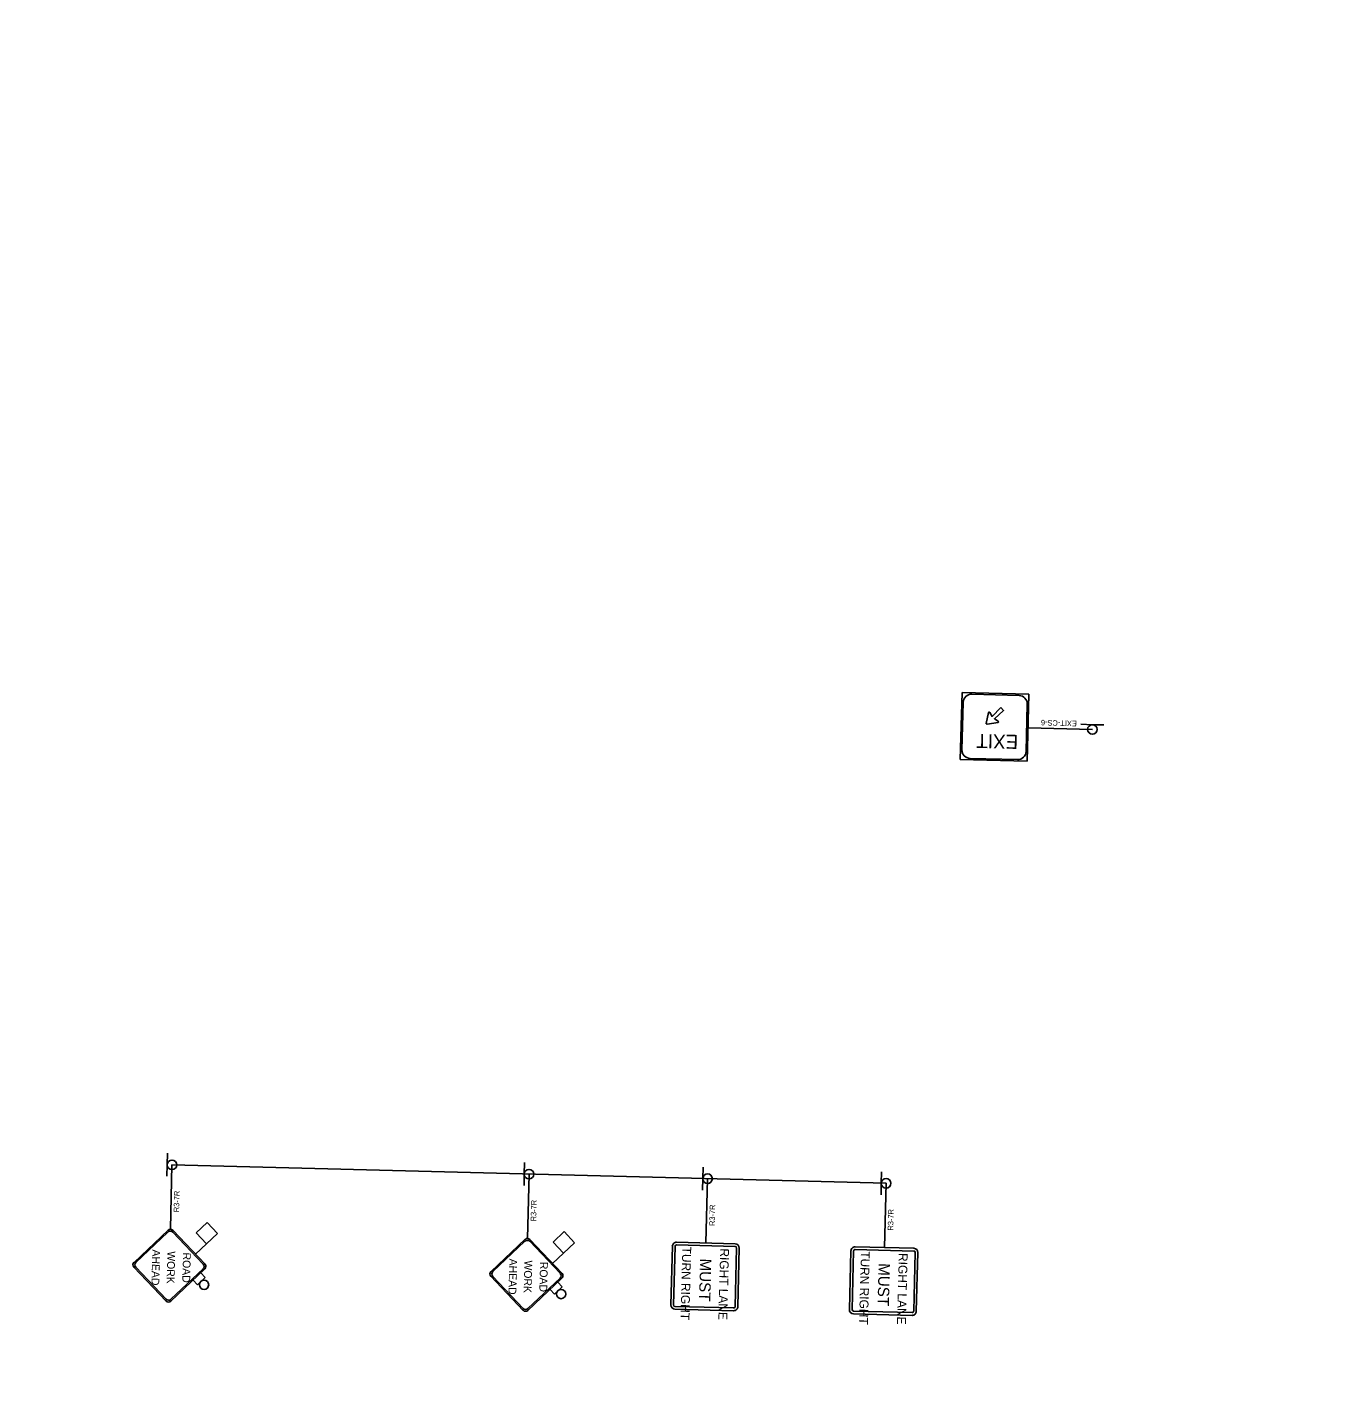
# Model space of a CAD drawing. Extents: x 2135767 to 2151731, y 141839 to 175894.
# Drawn here: x 2139087 to 2140193, y 169570 to 170711 of the extents above; entities that cross this region are included whole.
import ezdxf

# ---------------------------------------------------------------- set-up
doc = ezdxf.new("R2010")
doc.units = 0
for name, color, linetype in [('Default', 7, 'Continuous'), ('PR_Phasing_Detour_1', 7, 'Continuous'), ('PR_Traffic_Sign_Temp', 7, 'Continuous'), ('PR_Txt', 7, 'Continuous')]:
    doc.layers.add(name, color=color, linetype=linetype)

# ---------------------------------------------------------------- blocks, each defined once
blk = doc.blocks.new('FLSHFLAG')
at = {"layer": 'PR_Txt'}
for p, q in [((-1.2, 14.13), (0.84, 16.15)), ((0.84, 16.15), (4.9, 12.08)), ((0.82, 12.08), (-1.2, 14.13)), ((0.82, 12.08), (2.86, 14.11)), ((9.26, 14), (8.4, 13.15)), ((9.26, 14), (10.68, 12.58)), ((10.68, 12.58), (9.83, 11.72))]:
    blk.add_line(p, q, dxfattribs=at)
blk.add_circle((10.65, 13.84), 0.873, dxfattribs=at)

msp = doc.modelspace()

# ---------------------------------------------------------------- linework, layer by layer
at = {"layer": 'Default'}
for p, q in [((2139871.8, 170151.9), (2139870.3, 170095.6)), ((2139928, 170150.4), (2139871.8, 170151.9)), ((2139926.6, 170094.2), (2139928, 170150.4)), ((2139904.5, 170139.3), (2139897, 170131.9)), ((2139906.7, 170136.8), (2139904.5, 170139.3)), ((2139894, 170135.2), (2139892.1, 170126)), ((2139892.8, 170125.4), (2139902.1, 170126.8)), ((2139897, 170131.9), (2139895.2, 170135.1)), ((2139899, 170129.9), (2139906.7, 170136.8)), ((2139902.3, 170127.8), (2139899, 170129.9)), ((2139870.3, 170095.6), (2139926.6, 170094.2)), ((2139204.9, 169700.3), (2139176.3, 169673.2)), ((2139204.8, 169698.7), (2139177.9, 169673.2)), ((2139236, 169671.7), (2139208.8, 169700.2)), ((2139234.4, 169671.7), (2139208.8, 169698.6)), ((2139504.8, 169692.6), (2139476.2, 169665.5)), ((2139504.7, 169691), (2139477.8, 169665.4)), ((2139535.9, 169663.9), (2139508.7, 169692.5)), ((2139534.3, 169664), (2139508.7, 169690.9)), ((2139628.5, 169686.7), (2139627.2, 169637.5)), ((2139630.8, 169686.6), (2139629.5, 169637.4)), ((2139681.3, 169688.8), (2139632.1, 169690.1)), ((2139681.3, 169686.6), (2139632.1, 169687.9)), ((2139681.2, 169636.1), (2139682.5, 169685.3)), ((2139683.5, 169636), (2139684.7, 169685.2)), ((2139778.5, 169682.8), (2139777.2, 169633.6)), ((2139780.7, 169682.8), (2139779.4, 169633.6)), ((2139831.2, 169682.7), (2139782, 169684)), ((2139831.3, 169685), (2139782.1, 169686.2)), ((2139831.2, 169632.2), (2139832.4, 169681.4)), ((2139833.4, 169632.2), (2139834.7, 169681.4)), ((2139176.2, 169669.2), (2139203.3, 169640.7)), ((2139177.8, 169669.2), (2139203.4, 169642.3)), ((2139207.3, 169642.2), (2139234.3, 169667.7)), ((2139207.3, 169640.6), (2139235.8, 169667.7)), ((2139476.1, 169661.5), (2139503.2, 169632.9)), ((2139477.7, 169661.4), (2139503.3, 169634.5)), ((2139507.2, 169634.4), (2139534.2, 169660)), ((2139507.2, 169632.8), (2139535.7, 169659.9)), ((2139630.7, 169636.1), (2139679.9, 169634.9)), ((2139630.7, 169633.9), (2139679.9, 169632.6)), ((2139780.6, 169630), (2139829.8, 169628.7)), ((2139780.7, 169632.3), (2139829.9, 169631))]:
    msp.add_line(p, q, dxfattribs=at)
for points in [[(2139919.8, 170149.5), (2139880, 170150.5)], [(2139872.8, 170143.6), (2139871.7, 170103.8)], [(2139904.5, 170139.3), (2139897, 170131.9), (2139895.2, 170135.1)], [(2139902.3, 170127.8), (2139899, 170129.9), (2139906.7, 170136.8), (2139904.5, 170139.3)], [(2139925.6, 170102.4), (2139926.6, 170142.2)], [(2139894, 170135.2), (2139892.1, 170126)], [(2139892.8, 170125.4), (2139902.1, 170126.8)], [(2139878.6, 170096.6), (2139918.4, 170095.6)]]:
    msp.add_lwpolyline(points, dxfattribs=at)
for centre, radius, start, end in [((2139879.8, 170143.5), 7.03, 88.5212, 178.5212), ((2139919.6, 170142.4), 7.03, 358.5212, 88.5212), ((2139894.6, 170134.8), 0.699, 29.5789, 144.6011), ((2139894.6, 170134.8), 0.699, 29.5789, 144.6011), ((2139902.1, 170127.3), 0.507, 278.9476, 67.6995), ((2139902.1, 170127.3), 0.507, 278.9476, 67.6995), ((2139892.6, 170125.9), 0.543, 168.0494, 293.8906), ((2139892.6, 170125.9), 0.543, 168.0494, 293.8906), ((2139878.8, 170103.6), 7.03, 178.5212, 268.5212), ((2139918.6, 170102.6), 7.03, 268.5212, 358.5212), ((2139206.8, 169696.7), 2.81, 43.5212, 133.5212), ((2139206.8, 169698.3), 2.81, 43.5212, 133.5212), ((2139506.7, 169690.5), 2.81, 43.5212, 133.5212), ((2139506.7, 169688.9), 2.81, 43.5212, 133.5212), ((2139632, 169686.6), 3.52, 88.5212, 178.5212), ((2139632, 169686.6), 1.27, 88.5212, 178.5212), ((2139681.2, 169685.3), 3.52, 358.5212, 88.5212), ((2139681.2, 169685.3), 1.27, 358.5212, 88.5212), ((2139782, 169682.7), 3.52, 88.5212, 178.5212), ((2139782, 169682.7), 1.27, 88.5212, 178.5212), ((2139831.2, 169681.5), 1.27, 358.5212, 88.5212), ((2139831.2, 169681.5), 3.52, 358.5212, 88.5212), ((2139178.2, 169671.2), 2.81, 133.5212, 223.5212), ((2139179.8, 169671.1), 2.81, 133.5212, 223.5212), ((2139232.3, 169669.8), 2.81, 313.5212, 43.5212), ((2139233.9, 169669.7), 2.81, 313.5212, 43.5212), ((2139478.1, 169663.4), 2.81, 133.5212, 223.5212), ((2139479.7, 169663.4), 2.81, 133.5212, 223.5212), ((2139532.2, 169662), 2.81, 313.5212, 43.5212), ((2139533.8, 169662), 2.81, 313.5212, 43.5212), ((2139205.4, 169642.6), 2.81, 223.5212, 313.5212), ((2139205.4, 169644.2), 2.81, 223.5212, 313.5212), ((2139630.8, 169637.4), 3.52, 178.5212, 268.5212), ((2139630.8, 169637.4), 1.27, 178.5212, 268.5212), ((2139680, 169636.1), 1.27, 268.5212, 358.5212), ((2139680, 169636.1), 3.52, 268.5212, 358.5212), ((2139505.3, 169634.9), 2.81, 223.5212, 313.5212), ((2139505.3, 169636.5), 2.81, 223.5212, 313.5212), ((2139780.7, 169633.5), 3.52, 178.5212, 268.5212), ((2139780.7, 169633.5), 1.27, 178.5212, 268.5212), ((2139829.9, 169632.2), 3.52, 268.5212, 358.5212), ((2139829.9, 169632.2), 1.27, 268.5212, 358.5212)]:
    msp.add_arc(centre, radius, start, end, dxfattribs=at)
at = {"layer": 'PR_Phasing_Detour_1'}
msp.add_circle((2140069.5, 171591.4), 4302.2, dxfattribs=at)
at = {"layer": 'PR_Traffic_Sign_Temp'}
for p, q in [((2139981.3, 170120.9), (2139927.3, 170122.3)), ((2139981.4, 170124.9), (2139971.7, 170125.2)), ((2139991, 170124.7), (2139981.4, 170124.9)), ((2139204.4, 169764.8), (2139204.2, 169755.2)), ((2139204.2, 169755.2), (2139204, 169745.5)), ((2139208.2, 169755.1), (2139206.9, 169701.1)), ((2139504.3, 169757.1), (2139504.1, 169747.4)), ((2139654.3, 169753.2), (2139654.1, 169743.6)), ((2139504.1, 169747.4), (2139503.9, 169737.8)), ((2139508.1, 169747.3), (2139506.8, 169693.3)), ((2139654.1, 169743.6), (2139653.8, 169733.9)), ((2139658.1, 169743.5), (2139656.7, 169689.5)), ((2139804, 169739.7), (2139803.8, 169730)), ((2139804.2, 169749.3), (2139804, 169739.7)), ((2139808, 169739.6), (2139806.7, 169685.6))]:
    msp.add_line(p, q, dxfattribs=at)
msp.add_lwpolyline([(2139808, 169739.6), (2139208.2, 169755.1)], dxfattribs=at)
for centre in [(2139981.3, 170120.9), (2139208.2, 169755.1), (2139508.1, 169747.3), (2139658.1, 169743.5), (2139808, 169739.6)]:
    msp.add_circle(centre, 4, dxfattribs=at)

# ---------------------------------------------------------------- block references
at = {"layer": 'PR_Txt', "xscale": 4.4291250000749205, "yscale": 4.42912500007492, "rotation": -91.47881942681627}
for p in [(2139175.1, 169703.1), (2139475, 169695.3)]:
    msp.add_blockref('FLSHFLAG', p, dxfattribs=at)

# ---------------------------------------------------------------- texts
at = {"layer": 'Default'}
for s, height, rotation, p in [('EXIT-CS-6', 4.66, 178.5212, (2139968.3, 170128.2)), ('EXIT', 11.81, 178.5212, (2139919.1, 170116.3)), ('R3-7R', 4.66, 88.5859, (2139214.2, 169715.3)), ('R3-7R', 4.66, 88.5859, (2139514.1, 169707.6)), ('R3-7R', 4.66, 88.5859, (2139664.1, 169703.7)), ('R3-7R', 4.66, 88.5859, (2139814, 169699.9)), ('AHEAD', 6.56, 268.5212, (2139191.7, 169684.1)), ('WORK', 6.56, 268.5212, (2139204.4, 169682.6)), ('TURN RIGHT', 7.48, 268.5212, (2139636.9, 169686.5)), ('RIGHT LANE', 7.48, 268.5212, (2139668.7, 169685)), ('TURN RIGHT', 7.48, 268.5212, (2139786.9, 169682.6)), ('ROAD', 6.56, 268.5212, (2139217.5, 169681.5)), ('AHEAD', 6.56, 268.5212, (2139491.6, 169676.4)), ('WORK', 6.56, 268.5212, (2139504.3, 169674.9)), ('ROAD', 6.56, 268.5212, (2139517.4, 169673.7)), ('MUST', 9.5, 268.5212, (2139651.8, 169676.5)), ('MUST', 9.5, 268.5212, (2139801.8, 169672.6)), ('RIGHT LANE', 7.48, 268.5212, (2139818.7, 169681.1))]:
    msp.add_text(s, height=height, rotation=rotation, dxfattribs=at).set_placement(p)

doc.saveas('drawing.dxf')
